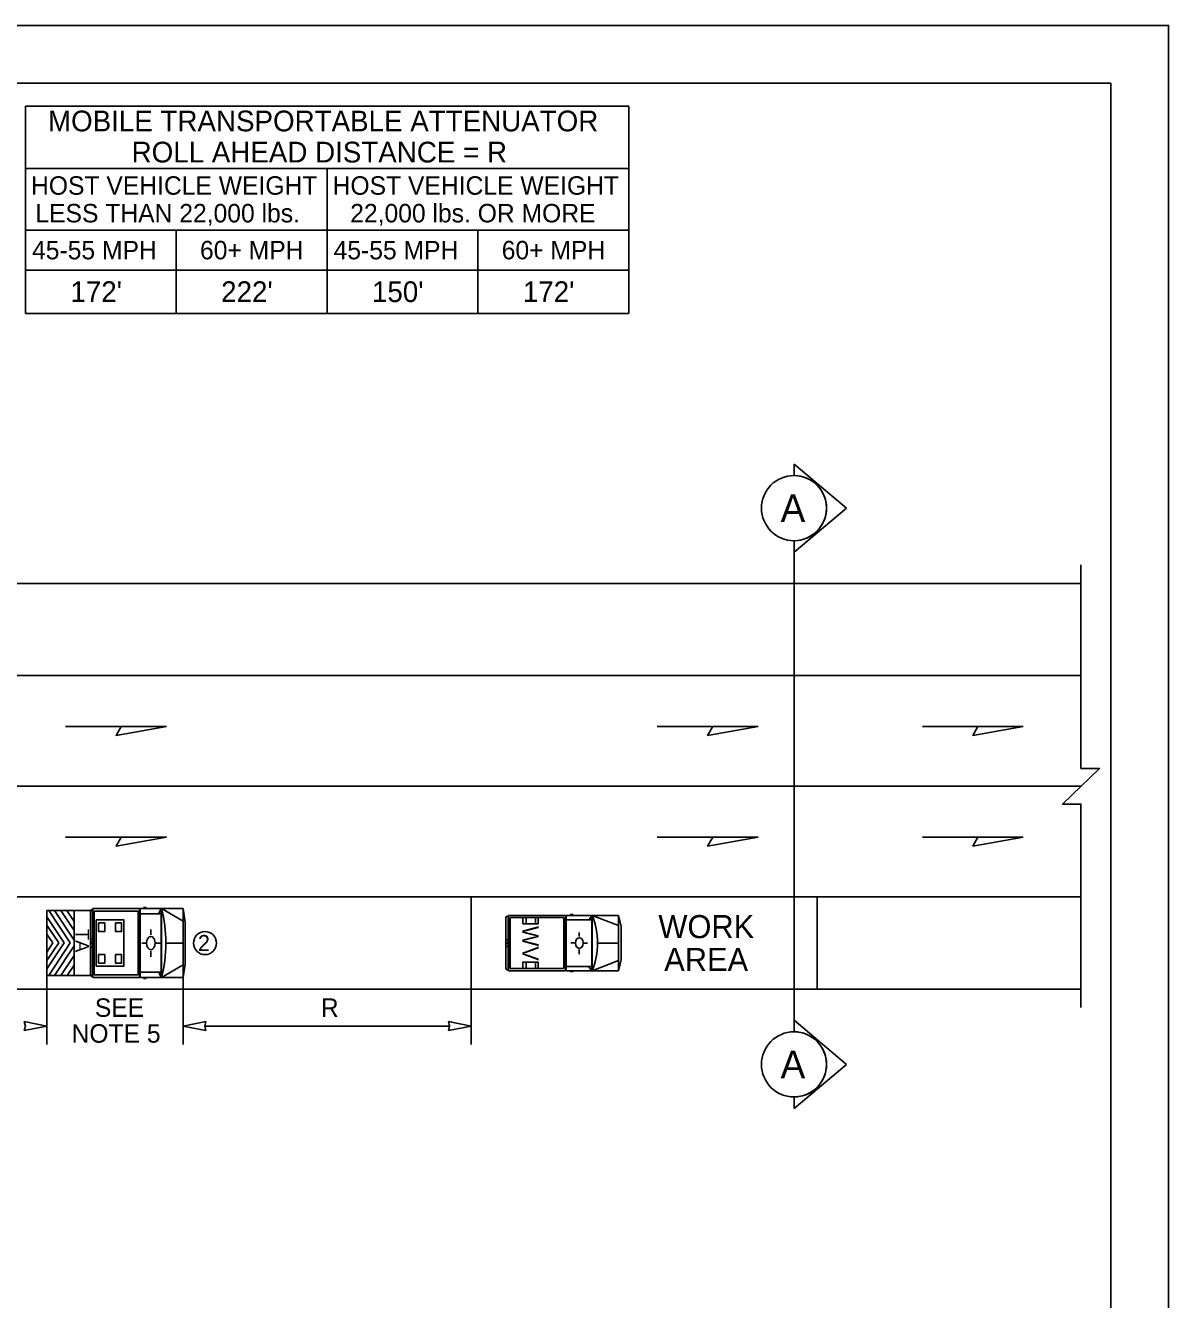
# Model space of a CAD drawing. Extents: x 0 to 17, y 0 to 11.
# Drawn here: x 12.04 to 17, y 5.47 to 11 of the extents above; entities that cross this region are included whole.
import ezdxf

# ---------------------------------------------------------------- set-up
doc = ezdxf.new("R2010")
doc.units = 0
for name, color, linetype in [('RD_ED_ShoulderPavedEdge', 7, 'Continuous'), ('RD_MK_LineEdgeWhite', 7, 'Continuous'), ('RD_MK_LineEdgeYellow', 7, 'Continuous'), ('RD_MK_LineLane', 7, 'Continuous'), ('SH_GI_PlotLimits', 7, 'Continuous'), ('SH_GI_SheetBorder3', 7, 'Continuous'), ('SH_TI_Tables', 7, 'Continuous'), ('SH_TI_WZSectionCut', 7, 'Continuous'), ('TR_WZ_ProtectiveVehicle', 7, 'Continuous'), ('TR_WZ_TransportableAttenuator', 7, 'Continuous'), ('TR_WZ_WorkZoneDetails', 7, 'Continuous'), ('TR_WZ_WorkZoneTextCurrent', 7, 'Continuous')]:
    doc.layers.add(name, color=color, linetype=linetype)

msp = doc.modelspace()

# ---------------------------------------------------------------- linework, layer by layer
at = {"layer": 'RD_ED_ShoulderPavedEdge'}
for p, q in [((1.8283, 8.5807), (16.62, 8.5807)), ((1.8283, 6.8207), (16.62, 6.8207))]:
    msp.add_line(p, q, dxfattribs=at)
at = {"layer": 'RD_MK_LineEdgeWhite'}
msp.add_line((1.8283, 7.2207), (16.62, 7.2207), dxfattribs=at)
at = {"layer": 'RD_MK_LineEdgeYellow'}
msp.add_line((1.8283, 8.1807), (16.62, 8.1807), dxfattribs=at)
at = {"layer": 'RD_MK_LineLane'}
msp.add_line((16.62, 7.7007), (1.8283, 7.7007), dxfattribs=at)
at = {"layer": 'SH_GI_PlotLimits'}
msp.add_lwpolyline([(0, 11), (17, 11), (17, 0), (0, 0)], close=True, dxfattribs=at)
at = {"layer": 'SH_GI_SheetBorder3'}
for p, q in [((1, 10.75), (16.75, 10.75)), ((16.75, 10.75), (16.75, 0.25))]:
    msp.add_line(p, q, dxfattribs=at)
at = {"layer": 'SH_TI_Tables'}
for p, q in [((12.0418, 9.7515), (12.0418, 10.65)), ((12.0418, 10.65), (14.6587, 10.65)), ((14.6587, 9.7515), (14.6587, 10.65)), ((12.0418, 10.3797), (14.6587, 10.3797)), ((13.3495, 9.7515), (13.3495, 10.3797)), ((12.0418, 10.1123), (13.3495, 10.1123)), ((12.6957, 9.7515), (12.6957, 10.1123)), ((13.3495, 10.1123), (14.6587, 10.1123)), ((14.0041, 9.7515), (14.0041, 10.1123)), ((12.0418, 9.9395), (12.6957, 9.9395)), ((12.6957, 9.9395), (13.3495, 9.9395)), ((13.3495, 9.9395), (14.0041, 9.9395)), ((14.0041, 9.9395), (14.6587, 9.9395)), ((12.0418, 9.7515), (14.6587, 9.7515))]:
    msp.add_line(p, q, dxfattribs=at)
at = {"layer": 'SH_TI_WZSectionCut'}
for p, q in [((15.3753, 9.0481), (15.3753, 9.098)), ((15.3753, 9.098), (15.6034, 8.9069)), ((15.6034, 8.9069), (15.3753, 8.7158)), ((15.3753, 8.7158), (15.3753, 8.7657)), ((15.3753, 8.7657), (15.3753, 6.6358)), ((15.3753, 6.6857), (15.3753, 6.6358)), ((15.6034, 6.4945), (15.3753, 6.6857)), ((15.3753, 6.3034), (15.6034, 6.4945)), ((15.3753, 6.3533), (15.3753, 6.3034))]:
    msp.add_line(p, q, dxfattribs=at)
for centre in [(15.3753, 8.9069), (15.3753, 6.4945)]:
    msp.add_circle(centre, 0.1412, dxfattribs=at)
for centre in [(15.3753, 8.9069), (15.3753, 6.4945)]:
    msp.add_arc(centre, 0.1412, 269.9978, 90.0022, dxfattribs=at)
at = {"layer": 'TR_WZ_ProtectiveVehicle'}
for p, q in [((14.1253, 6.912), (14.1253, 7.1295)), ((14.1306, 7.1368), (14.136, 7.1368)), ((14.136, 6.9047), (14.136, 7.1368)), ((14.1368, 7.1407), (14.3837, 7.1407)), ((14.1368, 6.9007), (14.1368, 7.1407)), ((14.1438, 6.9103), (14.1438, 7.1312)), ((14.1438, 7.1312), (14.3767, 7.1312)), ((14.1995, 7.1312), (14.1995, 7.1035)), ((14.2127, 7.1312), (14.2127, 7.1035)), ((14.2535, 7.1312), (14.2535, 7.1035)), ((14.2654, 7.1312), (14.2654, 7.1035)), ((14.3767, 6.9103), (14.3767, 7.1312)), ((14.3837, 6.9007), (14.3837, 7.1407)), ((14.387, 6.9007), (14.387, 7.1407)), ((14.6137, 7.1407), (14.387, 7.1407)), ((14.4179, 7.1441), (14.4043, 7.1441)), ((14.4863, 7.1221), (14.4983, 7.1407)), ((14.4983, 6.9007), (14.4983, 7.1407)), ((14.5003, 6.9007), (14.5003, 7.1407)), ((14.6137, 7.0968), (14.5003, 7.1407)), ((14.6137, 6.9007), (14.6137, 7.1407)), ((14.6137, 7.1407), (14.6248, 7.0923)), ((14.1995, 7.1035), (14.2654, 7.1035)), ((14.4983, 7.1221), (14.387, 7.1221)), ((14.6248, 6.9492), (14.6248, 7.0923)), ((14.1253, 7.0376), (14.136, 7.0331)), ((14.1282, 7.0207), (14.1331, 7.0207)), ((14.1306, 7.0173), (14.1306, 7.0241)), ((14.4068, 7.0216), (14.4247, 7.0212)), ((14.427, 7.0211), (14.427, 7.0211)), ((14.443, 7.0669), (14.4434, 7.0488)), ((14.48, 7.0206), (14.4649, 7.0206)), ((14.6137, 7.0207), (14.5226, 7.0207)), ((14.1253, 7.0038), (14.136, 7.0083)), ((14.4439, 6.9732), (14.4439, 6.9925)), ((14.1438, 6.9103), (14.3767, 6.9103)), ((14.1995, 6.9379), (14.2654, 6.9379)), ((14.1995, 6.9103), (14.1995, 6.9379)), ((14.2127, 6.9103), (14.2127, 6.9379)), ((14.2535, 6.9103), (14.2535, 6.9379)), ((14.2654, 6.9103), (14.2654, 6.9379)), ((14.4983, 6.9193), (14.387, 6.9193)), ((14.4983, 6.9007), (14.4838, 6.9193)), ((14.6137, 6.9447), (14.5003, 6.9007)), ((14.6137, 6.9007), (14.6248, 6.9492)), ((14.1306, 6.9047), (14.136, 6.9047)), ((14.1368, 6.9007), (14.3837, 6.9007)), ((14.6137, 6.9007), (14.387, 6.9007)), ((14.4179, 6.8973), (14.4043, 6.8973))]:
    msp.add_line(p, q, dxfattribs=at)
for centre, major_axis, start_param, end_param in [((14.1306, 7.1295), (0, 0.00732), 0, 1.570796), ((14.3383, 7.0208), (0, 0.2518), 4.215667, 5.208926), ((14.1306, 6.912), (0, -0.00732), 4.712389, 6.283185)]:
    msp.add_ellipse(centre, major_axis=major_axis, ratio=0.73155, start_param=start_param, end_param=end_param, dxfattribs=at)
for centre, major_axis in [((14.1306, 7.0207), (0, -0.00338)), ((14.4439, 7.0207), (0, -0.0231))]:
    msp.add_ellipse(centre, major_axis=major_axis, ratio=0.73155, dxfattribs=at)
at = {"layer": 'TR_WZ_TransportableAttenuator'}
for p, q in [((12.1344, 7.0986), (12.1344, 7.135)), ((12.2096, 7.0219), (12.1344, 7.135)), ((12.1344, 7.135), (12.1344, 7.0986)), ((12.1422, 7.1618), (12.1677, 7.1618)), ((12.1422, 7.1618), (12.2358, 7.021)), ((12.1677, 7.1618), (12.1422, 7.1618)), ((12.2524, 7.0334), (12.1677, 7.1618)), ((12.1954, 7.1618), (12.2208, 7.1618)), ((12.2208, 7.1618), (12.1954, 7.1618)), ((12.1954, 7.1618), (12.2524, 7.0749)), ((12.2524, 7.1141), (12.2208, 7.1618)), ((12.2524, 6.8802), (12.2524, 7.1618)), ((12.3329, 7.1618), (12.2524, 7.1618)), ((12.3234, 7.1567), (12.3234, 6.8848)), ((12.3278, 7.1658), (12.3322, 7.1658)), ((12.3322, 7.1658), (12.3322, 6.8756)), ((12.3329, 7.1707), (12.536, 7.1707)), ((12.3329, 7.1707), (12.3329, 6.8707)), ((12.3329, 7.1613), (12.3329, 6.8802)), ((12.3386, 7.1588), (12.3386, 6.8827)), ((12.3386, 7.1588), (12.5303, 7.1588)), ((12.5303, 7.1588), (12.5303, 6.8827)), ((12.536, 7.1707), (12.536, 6.8707)), ((12.5388, 7.1707), (12.5388, 6.8707)), ((12.7253, 7.1707), (12.5388, 7.1707)), ((12.6303, 7.1474), (12.5388, 7.1474)), ((12.5642, 7.1749), (12.553, 7.1749)), ((12.6303, 7.1707), (12.6185, 7.1474)), ((12.6303, 7.1707), (12.6303, 6.8707)), ((12.632, 7.1707), (12.632, 6.8707)), ((12.7253, 7.1158), (12.632, 7.1707)), ((12.7253, 7.1707), (12.7253, 6.8707)), ((12.7253, 7.1707), (12.7344, 7.1102)), ((12.1344, 7.0986), (12.1854, 7.0222)), ((12.2524, 7.1141), (12.2524, 7.0749)), ((12.2524, 7.0749), (12.2524, 7.1141)), ((12.5856, 7.0802), (12.5855, 7.0559)), ((12.7344, 7.1102), (12.7344, 6.9313)), ((12.1344, 6.9819), (12.1344, 7.0599)), ((12.1605, 7.0212), (12.1344, 7.0599)), ((12.1344, 7.0599), (12.1344, 6.9819)), ((12.1854, 7.0222), (12.1344, 6.9454)), ((12.1344, 6.9087), (12.2096, 7.0219)), ((12.1344, 6.9819), (12.1605, 7.0212)), ((12.2358, 7.021), (12.1421, 6.88)), ((12.2524, 7.0334), (12.2524, 7.0083)), ((12.2524, 7.0083), (12.2524, 7.0334)), ((12.3234, 7.0418), (12.3322, 7.0362)), ((12.3257, 7.0207), (12.3298, 7.0207)), ((12.3278, 7.0249), (12.3278, 7.0165)), ((12.5459, 7.0209), (12.5624, 7.0209)), ((12.567, 7.0202), (12.567, 7.0202)), ((12.6252, 7.0209), (12.6086, 7.0209)), ((12.7253, 7.0207), (12.6503, 7.0207)), ((12.1672, 6.88), (12.2524, 7.0083)), ((12.2524, 6.9669), (12.1947, 6.88)), ((12.2524, 6.9669), (12.2524, 6.9254)), ((12.2524, 6.9254), (12.2524, 6.9669)), ((12.3234, 6.9996), (12.3322, 7.0052)), ((12.5856, 6.9613), (12.5855, 6.9855)), ((12.1344, 6.9087), (12.1344, 6.9454)), ((12.1344, 6.9454), (12.1344, 6.9087)), ((12.2217, 6.88), (12.2524, 6.9254)), ((12.7253, 6.9256), (12.632, 6.8707)), ((12.7253, 6.8707), (12.7344, 6.9313)), ((12.1672, 6.88), (12.1421, 6.88)), ((12.1421, 6.88), (12.1672, 6.88)), ((12.2217, 6.88), (12.1947, 6.88)), ((12.1947, 6.88), (12.2217, 6.88)), ((12.3329, 6.8802), (12.2524, 6.8802)), ((12.3278, 6.8756), (12.3322, 6.8756)), ((12.3329, 6.8707), (12.536, 6.8707)), ((12.3386, 6.8827), (12.5303, 6.8827)), ((12.6303, 6.894), (12.5388, 6.894)), ((12.7253, 6.8707), (12.5388, 6.8707)), ((12.5642, 6.8665), (12.553, 6.8665)), ((12.6205, 6.894), (12.6303, 6.8707))]:
    msp.add_line(p, q, dxfattribs=at)
for points in [[(12.2524, 6.88), (12.1344, 6.88), (12.1344, 7.1618), (12.2524, 7.1618)], [(12.3486, 7.1207), (12.4686, 7.1207), (12.4686, 6.9207), (12.3486, 6.9207)], [(12.3586, 7.1082), (12.3853, 7.1082), (12.3853, 7.0707), (12.3586, 7.0707)], [(12.4586, 7.1082), (12.432, 7.1082), (12.432, 7.0707), (12.4586, 7.0707)], [(12.3586, 6.9707), (12.3853, 6.9707), (12.3853, 6.9332), (12.3586, 6.9332)], [(12.4586, 6.9707), (12.432, 6.9707), (12.432, 6.9332), (12.4586, 6.9332)]]:
    msp.add_lwpolyline(points, close=True, dxfattribs=at)
msp.add_lwpolyline([(12.2524, 7.1618), (12.1344, 7.1618), (12.1344, 6.88), (12.2524, 6.8802)], dxfattribs=at)
for centre, major_axis, start_param, end_param in [((12.3278, 7.1566), (0, 0.00916), 6.283185, 7.853982), ((12.4987, 7.0207), (0, 0.3148), 4.215852, 5.209111), ((12.3278, 6.8848), (0, -0.00916), 4.712389, 6.283185)]:
    msp.add_ellipse(centre, major_axis=major_axis, ratio=0.481608, start_param=start_param, end_param=end_param, dxfattribs=at)
for centre, major_axis, ratio in [((12.3278, 7.0207), (0, -0.00423), 0.481608), ((12.5855, 7.0207), (0, -0.0289), 0.642144), ((12.5855, 7.0207), (0, 0.0289), 0.642144)]:
    msp.add_ellipse(centre, major_axis=major_axis, ratio=ratio, dxfattribs=at)
at = {"layer": 'TR_WZ_WorkZoneDetails'}
for p, q in [((12.4567, 7.96), (12.2156, 7.96)), ((15.0225, 7.96), (14.7814, 7.96)), ((16.1734, 7.96), (15.9323, 7.96)), ((12.4567, 7.48), (12.2156, 7.48)), ((15.0225, 7.48), (14.7814, 7.48)), ((16.1734, 7.48), (15.9323, 7.48)), ((12.1346, 6.88), (12.1346, 6.5807)), ((12.7253, 6.8707), (12.7253, 6.5807)), ((13.9753, 6.8207), (13.9753, 6.5807)), ((13.8815, 6.6607), (12.819, 6.6607))]:
    msp.add_line(p, q, dxfattribs=at)
msp.add_lwpolyline([(16.62, 6.7407), (16.62, 7.6233), (16.5399, 7.6233), (16.7, 7.7782), (16.62, 7.7782), (16.62, 8.6607)], dxfattribs=at)
for points in [[(12.6533, 7.96), (12.4344, 7.9214), (12.4567, 7.96)], [(15.2191, 7.96), (15.0003, 7.9214), (15.0225, 7.96)], [(16.37, 7.96), (16.1512, 7.9214), (16.1734, 7.96)], [(12.6533, 7.48), (12.4344, 7.4414), (12.4567, 7.48)], [(15.2191, 7.48), (15.0003, 7.4414), (15.0225, 7.48)], [(16.37, 7.48), (16.1512, 7.4414), (16.1734, 7.48)], [(13.9753, 6.8207), (13.9753, 7.2207), (15.4753, 7.2207), (15.4753, 6.8207)], [(12.1346, 6.6607), (12.0363, 6.68), (12.0408, 6.6607), (12.0363, 6.6415)], [(12.7253, 6.6607), (12.8236, 6.68), (12.819, 6.6607), (12.8236, 6.6415)], [(13.9753, 6.6607), (13.877, 6.68), (13.8815, 6.6607), (13.877, 6.6415)]]:
    msp.add_lwpolyline(points, close=True, dxfattribs=at)
msp.add_circle((12.8201, 7.0207), 0.05, dxfattribs=at)

# ---------------------------------------------------------------- texts
at = {"layer": 'SH_TI_Tables'}
for s, height, p in [('MOBILE TRANSPORTABLE ATTENUATOR', 0.09, (12.1389, 10.5408)), ('ROLL AHEAD DISTANCE = R', 0.09, (12.5018, 10.4058)), ('HOST VEHICLE WEIGHT', 0.08, (12.0654, 10.266)), ('HOST VEHICLE WEIGHT', 0.08, (13.3738, 10.266)), ('LESS THAN 22,000 lbs.', 0.08, (12.0844, 10.146)), ('22,000 lbs. OR MORE', 0.08, (13.4501, 10.146)), ('45-55 MPH', 0.08, (12.0699, 9.9859)), ('60+ MPH', 0.08, (12.7984, 9.9859)), ('45-55 MPH', 0.08, (13.378, 9.9859)), ('60+ MPH', 0.08, (14.1073, 9.9859)), ("172'", 0.09, (12.2363, 9.8005)), ("222'", 0.09, (12.8901, 9.8005)), ("150'", 0.09, (13.5444, 9.8005)), ("172'", 0.09, (14.199, 9.8005))]:
    msp.add_text(s, height=height, rotation=360, dxfattribs=at).set_placement(p)
at = {"layer": 'SH_TI_WZSectionCut'}
for rotation, p in [(359.99, (15.3171, 8.8469)), (0.01, (15.3171, 6.4345))]:
    msp.add_text('A', height=0.12, rotation=rotation, dxfattribs=at).set_placement(p)
at = {"layer": 'TR_WZ_ProtectiveVehicle'}
msp.add_text('WV', height=0.07, rotation=270, dxfattribs=at).set_placement((14.1974, 7.0948))
at = {"layer": 'TR_WZ_TransportableAttenuator'}
msp.add_text('TA', height=0.06, rotation=270, dxfattribs=at).set_placement((12.2571, 7.0827))
at = {"layer": 'TR_WZ_WorkZoneDetails'}
for s, height, p in [('WORK', 0.1, (14.7868, 7.042)), ('2', 0.07, (12.7894, 6.9857)), ('AREA', 0.1, (14.8122, 6.8995))]:
    msp.add_text(s, height=height, dxfattribs=at).set_placement(p)
at = {"layer": 'TR_WZ_WorkZoneTextCurrent'}
for s, p in [('SEE', (12.3424, 6.7007)), ('R', (13.3227, 6.7007)), ('NOTE 5', (12.2411, 6.5887))]:
    msp.add_text(s, height=0.08, dxfattribs=at).set_placement(p)

doc.saveas('drawing.dxf')
